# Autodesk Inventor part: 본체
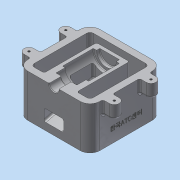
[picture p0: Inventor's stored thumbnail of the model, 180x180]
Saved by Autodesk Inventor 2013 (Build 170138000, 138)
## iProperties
Created: 2018-01
Part Number: 본체
Material: 알루미늄 6061
Document SubType Name: Modeling
Designer: dgall
Density: 2.71 g/cm^3
Mass: 998.262 g
Surface Area: 836.256 cm^2
Volume: 368.362 cm^3
Author: dgall
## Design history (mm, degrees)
sketch "스케치1"
  geometry: L1 (-55, 55)-(55, 55); L2 (55, 55)-(55, -55); L3 (55, -55)-(-55, -55); L4 (-55, -55)-(-55, 55); L5 (45, 45)-(-45, 45); L6 (-45, 45)-(-45, -45); L7 (-45, -45)-(45, -45); L8 (45, -45)-(45, 45); 3 further points
  constraints: 16 end point, 2 midpoint, 2 parallel, 1 horizontal, 1 horizontal alignment, 1 perpendicular, 1 vertical alignment
  dimensions: "d0" = 110 distance of L1.start L1.end; "d2" = 110 distance of L1.end L2.end; "d3" = 10 distance between parallel lines of L1 L5; "d4" = 10 distance between parallel lines of L4 L6; "d5" = 10 distance between parallel lines of L2 L8; "d6" = 10 distance between parallel lines of L3 L7
extrude "돌출1" new body sketch "스케치1" stored distance "d7" = 65; taper "d8" = 0 deg
sketch "스케치3"
  geometry: L1 (-45, -32.5)-(-45, 32.5) reference; L2 (45, -32.5)-(-45, -32.5) reference; L3 (45, -32.5)-(45, 32.5) reference; L4 (-45, 32.5)-(45, 32.5) reference; L5 (35, 32.5)-(35, -2.5); L6 (35, -2.5)-(-45, -23.936); L7 (55, -32.5)-(55, 32.5) reference; 1 further point
  constraints: 4 end point, 2 point on line, 1 perpendicular
  dimensions: "d9" = 20 distance between parallel lines of L7 L5; "d10" = 30 distance from line of L2 L5.end; "d11" = 105 deg angle of L6 L1
extrude "돌출2" join sketch "스케치3" stored distance "d12" = 50; taper "d13" = 0 deg
sketch "스케치4"
  geometry: L1 (-55, 55)-(-55, -55) reference; L2 (-55, -55)-(55, -55) reference; L3 (55, -55)-(55, 55) reference; L4 (-55, -35.5)-(-65, -35.5); L5 (-65, -20.5)-(-55, -20.5); L6 (-55, 20.5)-(-65, 20.5); L7 (-65, 35.5)-(-55, 35.5); A1 r 7.5 centre (-65, -28) between (-65, -20.5) and (-65, -35.5); A2 r 7.5 centre (-65, 28) between (-65, 35.5) and (-65, 20.5); 1 further point
  constraints: 8 end point, 4 perpendicular, 4 point on circle, 4 point on line, 4 tangent, 2 centre point, 2 vertical alignment, 1 equal radius, 1 parallel
  dimensions: "d14" = 7.5 radius of A1; "d16" = 27 distance from line of L2 A1.centre; "d17" = 56 distance of A2.centre A1.centre; "d18" = 10 distance of L5.start L5.end
extrude "돌출3" join sketch "스케치4" distance "d19" = 20; taper "d20" = 0 deg
sketch "스케치6"
  geometry: L1 (-45, 32.5)-(-45, -23.936) reference; L2 (-45, 32.5)-(35, 32.5) reference; L3 (35, 32.5)-(35, -2.5) reference; L4 (35, -2.5)-(-45, -23.936) reference; L5 (-20.5, 12.5)-(-20.5, 32.5) reference; L6 (20.5, 32.5)-(-20.5, 32.5) reference; L7 (20.5, 32.5)-(20.5, 12.5) reference; L8 (20.5, 12.5)-(35.5, 12.5) reference; L9 (35.5, 12.5)-(35.5, 32.5) reference; L10 (55, 32.5)-(35.5, 32.5) reference; L11 (55, -32.5)-(55, 32.5) reference; L12 (-55, -32.5)-(55, -32.5) reference; L13 (-55, 32.5)-(-55, -32.5) reference; L14 (-35.5, 32.5)-(-55, 32.5) reference; L15 (-35.5, 32.5)-(-35.5, 12.5) reference; L16 (-35.5, 12.5)-(-20.5, 12.5) reference; L17 (-55, 32.5)-(35.5, 32.5); L18 (-55, 32.5)-(-55, 25); L19 (-55, 25)-(-36, 25); L20 (-36, 25)-(-36, 16.5); L21 (-36, 16.5)-(-22, 16.5); L22 (-22, 16.5)-(-22, 12.5); L23 (-22, 12.5)-(25, 12.5); L24 (25, 12.5)-(25, 17.5); L25 (25, 17.5)-(30, 17.5); L26 (30, 17.5)-(30, 32.5); 1 further point
  constraints: 20 end point, 5 perpendicular, 4 parallel, 2 point on line
  dimensions: "d21" = 7.5 distance between parallel lines of L14 L19; "d22" = 16 distance between parallel lines of L2 L21; "d23" = 20 distance between parallel lines of L2 L23; "d24" = 15 distance between parallel lines of L6 L25; "d25" = 19 distance of L18.end L19.end; "d26" = 14 distance of L20.end L21.end; "d27" = 47 distance of L22.end L23.end; "d28" = 5 distance of L24.end L25.end
revolve "회전1" sketch "스케치6" stored, may be unused: angle "d29" = 90 deg
sketch "스케치7"
  geometry: L1 (35, -2.5)-(-45, -23.936) reference; L2 (20, -1.343)-(-55, -21.439); L3 (-20.5, 12.5)-(-20.5, 32.5) reference; L4 (20.5, 32.5)-(-20.5, 32.5) reference; L5 (20.5, 32.5)-(20.5, 12.5) reference; L6 (20.5, 12.5)-(35.5, 12.5) reference; L7 (35.5, 12.5)-(35.5, 32.5) reference; L8 (55, 32.5)-(35.5, 32.5) reference; L9 (55, -32.5)-(55, 32.5) reference; L10 (-55, -32.5)-(55, -32.5) reference; L11 (-55, 32.5)-(-55, -32.5) reference; L12 (-35.5, 32.5)-(-55, 32.5) reference; L13 (-35.5, 32.5)-(-35.5, 12.5) reference; L14 (-35.5, 12.5)-(-20.5, 12.5) reference; L15 (-17, 6.743)-(-55, -3.439); L16 (20, -1.343)-(20, 20.901); L17 (-22, 12.5)-(-22, 32.5) reference; L18 (-55, -3.439)-(-55, -21.439); L19 (-17, 6.743)-(-17, 20.901); L20 (-17, 20.901)-(20, 20.901); 1 further point
  constraints: 12 end point, 2 parallel, 2 perpendicular, 2 point on line
  dimensions: "d30" = 5 distance between parallel lines of L1 L2; "d32" = 18 distance of L2.end L15.end; "d33" = 75 deg angle of L11 L15; "d36" = 37 distance of L19.end L16.end; "d37" = 5 distance between parallel lines of L19 L17; "d38" = 22.24378 distance from line of L2.start L20
extrude "돌출4" cut sketch "스케치7" stored distance "d39" = 30; taper "d40" = 0 deg
fillet "모깎기1" dims "d41" = 1
chamfer "모따기1" distance "d42" = 1; stored, may be unused: second distance "d43" = 2, angle "d44" = 45 deg
fillet "모깎기3" dims "d46" = 3
fillet "모깎기4" dims "d47" = 3
fillet "모깎기5" dims "d48" = 3
fillet "모깎기6" dims "d49" = 15
fillet "모깎기7" dims "d50" = 5
sketch "스케치10"
  geometry: A1 r 7.5 centre (65, -28) between (65, -35.5) and (65, -20.5) reference; A2 r 7.5 centre (65, 28) between (65, 20.5) and (65, 35.5) reference; A3 r 7.5 centre (-65, 28) between (-65, 35.5) and (-65, 20.5) reference; A4 r 7.5 centre (-65, -28) between (-65, -20.5) and (-65, -35.5) reference; 5 further points
  constraints: 4 coincident
hole "구멍1" sketch "스케치10" at (-65, -28), (-65, 28), (65, 28), (65, -28) diameter "d57" = 3.242; stored, may be unused: countersink angle "d61" = 90 deg, drill point angle "d63" = 118 deg; dims "d58" = 9, "d59" = 4, "d60" = 2, "d62" = 11
fillet "모깎기10" dims "d64" = 3
fillet "모깎기11" dims "d65" = 3
fillet "모깎기12" dims "d66" = 3
fillet "모깎기13" dims "d67" = 3
fillet "모깎기14" dims "d68" = 3
fillet "모깎기15" dims "d69" = 3
fillet "모깎기17" dims "d71" = 3
fillet "모깎기18" dims "d72" = 3
fillet "모깎기19" dims "d73" = 3
fillet "모깎기20" dims "d74" = 3
sketch "스케치12" dims "d0" = 110, "d2" = 110, "d3" = 10, "d4" = 10, "d5" = 10, "d6" = 10
  geometry: L1 (0, 80)-(0, 0) reference; L2 (-65, -15)-(0, -15) reference; 2 further points
  constraints: 1 other
  dimensions: "d75" = 20 distance from line of L1 point (-20, 40); "d76" = 55 distance from line of L2 point (-20, 40)
feature "엠보싱2" sketch "스케치12" dims "d0" = 110, "d2" = 110, "d3" = 10, "d4" = 10, "d5" = 10, "d6" = 10, "d77" = 0.5, "d78" = 0
node "솔리드1"
mirror "대칭1"
node "투영된 루프1"
node "투영된 루프2"
node "투영된 루프3"
node "투영된 루프4"
